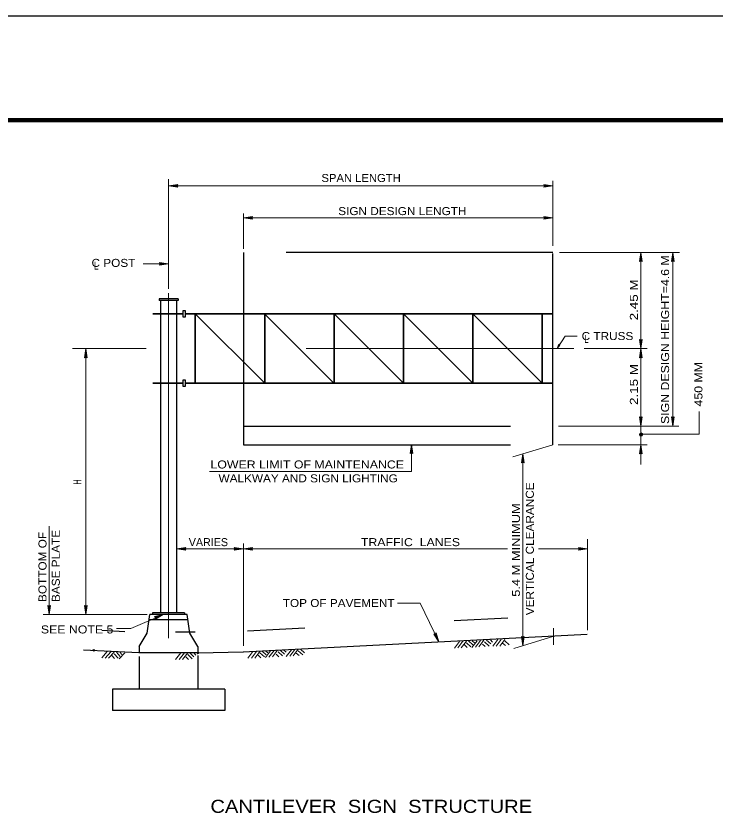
# Model space of a CAD drawing. Extents: x 312601.858 to 312602.699, y 144420.109 to 144420.704.
# Drawn here: x 312602.229 to 312602.4911, y 144420.4049 to 144420.7035 of the extents above; entities that cross this region are included whole.
import ezdxf
from ezdxf.enums import TextEntityAlignment as Align

# ---------------------------------------------------------------- set-up
doc = ezdxf.new("R2010")
doc.units = 0
doc.header["$LTSCALE"] = 0.0012
doc.header["$PDMODE"] = 32
doc.header["$PDSIZE"] = 0.0006
doc.linetypes.add('DOT_DASHED', pattern=[7.7, 5, -1.2, 0.3, -1.2])
doc.linetypes.add('LONG_DASHED', pattern=[7.5, 6, -1.5])
doc.layers.add('1', color=7, linetype='Continuous', lineweight=13)
doc.layers.add('39', color=7, linetype='Continuous', lineweight=13)

msp = doc.modelspace()

# ---------------------------------------------------------------- hatches: boundary and pattern name
at = {"layer": '39'}
for points in [[(312602.2894, 144420.6399), (312602.2897, 144420.6394), (312602.2863, 144420.6399), (312602.2897, 144420.6404)], [(312602.4272, 144420.6399), (312602.4269, 144420.6404), (312602.4303, 144420.6399), (312602.4269, 144420.6394)], [(312602.3174, 144420.6279), (312602.3177, 144420.6274), (312602.3143, 144420.6279), (312602.3177, 144420.6284)], [(312602.4272, 144420.6279), (312602.4269, 144420.6284), (312602.4303, 144420.6279), (312602.4269, 144420.6274)], [(312602.4272, 144420.6279), (312602.4269, 144420.6284), (312602.4303, 144420.6279), (312602.4269, 144420.6274)], [(312602.4633, 144420.6118), (312602.4628, 144420.6115), (312602.4633, 144420.6149), (312602.4638, 144420.6115)], [(312602.4633, 144420.6118), (312602.4628, 144420.6115), (312602.4633, 144420.6149), (312602.4638, 144420.6115)], [(312602.4753, 144420.6118), (312602.4748, 144420.6115), (312602.4753, 144420.6149), (312602.4758, 144420.6115)], [(312602.4753, 144420.6118), (312602.4748, 144420.6115), (312602.4753, 144420.6149), (312602.4758, 144420.6115)], [(312602.2832, 144420.6107), (312602.2829, 144420.6112), (312602.2863, 144420.6107), (312602.2829, 144420.6102)], [(312602.2832, 144420.6107), (312602.2829, 144420.6112), (312602.2863, 144420.6107), (312602.2829, 144420.6102)], [(312602.4328, 144420.5802), (312602.433, 144420.5802), (312602.4319, 144420.5789), (312602.4326, 144420.5805)], [(312602.4633, 144420.582), (312602.4638, 144420.5823), (312602.4633, 144420.5789), (312602.4628, 144420.5823)], [(312602.4633, 144420.582), (312602.4638, 144420.5823), (312602.4633, 144420.5789), (312602.4628, 144420.5823)], [(312602.2553, 144420.5758), (312602.2548, 144420.5755), (312602.2553, 144420.5789), (312602.2558, 144420.5755)], [(312602.2553, 144420.5758), (312602.2548, 144420.5755), (312602.2553, 144420.5789), (312602.2558, 144420.5755)], [(312602.4633, 144420.5758), (312602.4628, 144420.5755), (312602.4633, 144420.5789), (312602.4638, 144420.5755)], [(312602.4633, 144420.5758), (312602.4628, 144420.5755), (312602.4633, 144420.5789), (312602.4638, 144420.5755)], [(312602.4633, 144420.553), (312602.4638, 144420.5533), (312602.4633, 144420.5499), (312602.4628, 144420.5533)], [(312602.4633, 144420.553), (312602.4638, 144420.5533), (312602.4633, 144420.5499), (312602.4628, 144420.5533)], [(312602.4753, 144420.553), (312602.4758, 144420.5533), (312602.4753, 144420.5499), (312602.4748, 144420.5533)], [(312602.4753, 144420.553), (312602.4758, 144420.5533), (312602.4753, 144420.5499), (312602.4748, 144420.5533)], [(312602.4753, 144420.553), (312602.4758, 144420.5533), (312602.4753, 144420.5499), (312602.4748, 144420.5533)], [(312602.4639, 144420.5463, 1), (312602.4629, 144420.5471, 1)], [(312602.4631, 144420.547, 1), (312602.4635, 144420.5466, 1)], [(312602.3773, 144420.5399), (312602.3768, 144420.5396), (312602.3773, 144420.543), (312602.3778, 144420.5396)], [(312602.4633, 144420.5398), (312602.4628, 144420.5395), (312602.4633, 144420.5429), (312602.4638, 144420.5395)], [(312602.4633, 144420.5398), (312602.4628, 144420.5395), (312602.4633, 144420.5429), (312602.4638, 144420.5395)], [(312602.4191, 144420.5364), (312602.4186, 144420.5361), (312602.4191, 144420.5395), (312602.4196, 144420.5361)], [(312602.2924, 144420.5039), (312602.2927, 144420.5034), (312602.2893, 144420.5039), (312602.2927, 144420.5044)], [(312602.2924, 144420.5039), (312602.2927, 144420.5034), (312602.2893, 144420.5039), (312602.2927, 144420.5044)], [(312602.3112, 144420.5039), (312602.3109, 144420.5044), (312602.3143, 144420.5039), (312602.3109, 144420.5034)], [(312602.3112, 144420.5039), (312602.3109, 144420.5044), (312602.3143, 144420.5039), (312602.3109, 144420.5034)], [(312602.3174, 144420.5039), (312602.3177, 144420.5034), (312602.3143, 144420.5039), (312602.3177, 144420.5044)], [(312602.3174, 144420.5039), (312602.3177, 144420.5034), (312602.3143, 144420.5039), (312602.3177, 144420.5044)], [(312602.4402, 144420.5039), (312602.4399, 144420.5044), (312602.4433, 144420.5039), (312602.4399, 144420.5034)], [(312602.4402, 144420.5039), (312602.4399, 144420.5044), (312602.4433, 144420.5039), (312602.4399, 144420.5034)], [(312602.2415, 144420.4824), (312602.242, 144420.4827), (312602.2415, 144420.4793), (312602.241, 144420.4827)], [(312602.2553, 144420.4824), (312602.2558, 144420.4827), (312602.2553, 144420.4793), (312602.2548, 144420.4827)], [(312602.2814, 144420.478), (312602.281, 144420.4785), (312602.2842, 144420.4793), (312602.2814, 144420.4775)], [(312602.3862, 144420.4719), (312602.3866, 144420.4724), (312602.3876, 144420.4691), (312602.3857, 144420.4719)], [(312602.4191, 144420.4707), (312602.4196, 144420.471), (312602.4191, 144420.4676), (312602.4186, 144420.471)]]:
    msp.add_hatch(color=256, dxfattribs=at).paths.add_polyline_path(points)

# ---------------------------------------------------------------- linework, layer by layer
at = {"layer": '1', "lineweight": 25}
for p, q in [((312601.8578, 144420.7035), (312602.6988, 144420.7035)), ((312602.3933, 144420.477), (312602.4135, 144420.478)), ((312602.3159, 144420.4732), (312602.3374, 144420.4743))]:
    msp.add_line(p, q, dxfattribs=at)
at = {"layer": '1'}
for p, q in [((312602.4852, 144420.5553), (312602.4852, 144420.5469)), ((312602.4633, 144420.5469), (312602.4852, 144420.5469)), ((312602.4303, 144420.5429), (312602.4153, 144420.5383)), ((312602.2415, 144420.5124), (312602.2415, 144420.4793)), ((312602.3721, 144420.4835), (312602.3806, 144420.4835)), ((312602.3876, 144420.4691), (312602.3806, 144420.4835)), ((312602.2392, 144420.4793), (312602.2782, 144420.4793)), ((312602.3987, 144420.4694), (312602.4003, 144420.4679)), ((312602.4, 144420.467), (312602.4019, 144420.4695)), ((312602.4001, 144420.4694), (312602.4009, 144420.4687)), ((312602.4013, 144420.4671), (312602.4032, 144420.4696)), ((312602.4026, 144420.4672), (312602.4045, 144420.4697)), ((312602.4055, 144420.4697), (312602.4071, 144420.4683)), ((312602.4069, 144420.4698), (312602.4077, 144420.469)), ((312602.4078, 144420.4674), (312602.4097, 144420.4699)), ((312602.4091, 144420.4675), (312602.411, 144420.47)), ((312602.4104, 144420.4675), (312602.4123, 144420.47)), ((312602.4123, 144420.4694), (312602.414, 144420.4679)), ((312602.4307, 144420.4712), (312602.4157, 144420.4666)), ((312602.3934, 144420.4667), (312602.3953, 144420.4692)), ((312602.3947, 144420.4668), (312602.3966, 144420.4693)), ((312602.396, 144420.4668), (312602.3979, 144420.4693)), ((312602.3972, 144420.4679), (312602.3982, 144420.4669)), ((312602.3979, 144420.4687), (312602.3996, 144420.4672)), ((312602.404, 144420.4682), (312602.405, 144420.4673)), ((312602.4047, 144420.4691), (312602.4064, 144420.4675)), ((312602.4115, 144420.4686), (312602.4126, 144420.4677)), ((312602.2612, 144420.4631), (312602.2633, 144420.4654)), ((312602.2625, 144420.463), (312602.2646, 144420.4653)), ((312602.2638, 144420.463), (312602.2659, 144420.4652)), ((312602.265, 144420.4639), (312602.266, 144420.4628)), ((312602.2659, 144420.4646), (312602.2674, 144420.4629)), ((312602.2667, 144420.4652), (312602.2681, 144420.4636)), ((312602.2677, 144420.4627), (312602.2699, 144420.465)), ((312602.2681, 144420.4651), (312602.2688, 144420.4643)), ((312602.2889, 144420.4625), (312602.2909, 144420.4649)), ((312602.2902, 144420.4625), (312602.2922, 144420.4649)), ((312602.2915, 144420.4625), (312602.2935, 144420.4649)), ((312602.2927, 144420.4635), (312602.2937, 144420.4625)), ((312602.2935, 144420.4643), (312602.2951, 144420.4627)), ((312602.2943, 144420.4649), (312602.2958, 144420.4634)), ((312602.2957, 144420.4649), (312602.2965, 144420.4641)), ((312602.316, 144420.4629), (312602.3179, 144420.4654)), ((312602.3173, 144420.463), (312602.3192, 144420.4655)), ((312602.3186, 144420.463), (312602.3205, 144420.4655)), ((312602.3198, 144420.4641), (312602.3208, 144420.4631)), ((312602.3205, 144420.4649), (312602.3222, 144420.4634)), ((312602.3213, 144420.4656), (312602.3229, 144420.4642)), ((312602.3226, 144420.4632), (312602.3245, 144420.4657)), ((312602.3227, 144420.4656), (312602.3235, 144420.4649)), ((312602.3239, 144420.4633), (312602.3258, 144420.4658)), ((312602.3252, 144420.4634), (312602.3271, 144420.4659)), ((312602.3266, 144420.4644), (312602.3276, 144420.4635)), ((312602.3273, 144420.4653), (312602.329, 144420.4638)), ((312602.3281, 144420.4659), (312602.3297, 144420.4645)), ((312602.3295, 144420.466), (312602.3303, 144420.4652)), ((312602.3304, 144420.4636), (312602.3323, 144420.4661)), ((312602.3317, 144420.4637), (312602.3336, 144420.4662)), ((312602.333, 144420.4638), (312602.3349, 144420.4663)), ((312602.3341, 144420.4648), (312602.3352, 144420.4639)), ((312602.3349, 144420.4657), (312602.3366, 144420.4642)), ((312602.3357, 144420.4663), (312602.3372, 144420.4649))]:
    msp.add_line(p, q, dxfattribs=at)
at = {"layer": '1', "linetype": 'LONG_DASHED', "lineweight": 25}
for p, q in [((312602.2613, 144420.4734), (312602.2699, 144420.4729)), ((312602.2889, 144420.4728), (312602.2963, 144420.4728))]:
    msp.add_line(p, q, dxfattribs=at)
at = {"layer": '1', "lineweight": 25}
for points in [[(312602.2917, 144420.5907), (312602.2917, 144420.5932), (312602.2925, 144420.5932), (312602.2925, 144420.5907)], [(312602.2917, 144420.5647), (312602.2917, 144420.5672), (312602.2925, 144420.5672), (312602.2925, 144420.5647)]]:
    msp.add_lwpolyline(points, close=True, dxfattribs=at)
at = {"layer": '1'}
msp.add_lwpolyline([(312602.4395, 144420.5836), (312602.435, 144420.5836), (312602.4319, 144420.5789)], dxfattribs=at)
at = {"layer": '39', "lineweight": 158}
msp.add_line((312601.9088, 144420.6645), (312602.6838, 144420.6645), dxfattribs=at)
at = {"layer": '39'}
for p, q in [((312602.2863, 144420.6424), (312602.2863, 144420.6013)), ((312602.4303, 144420.6399), (312602.2863, 144420.6399)), ((312602.4303, 144420.6174), (312602.4303, 144420.6418)), ((312602.3143, 144420.6295), (312602.3143, 144420.6163)), ((312602.4303, 144420.6279), (312602.3143, 144420.6279)), ((312602.4778, 144420.6149), (312602.4328, 144420.6149)), ((312602.4633, 144420.5789), (312602.4633, 144420.6149)), ((312602.4753, 144420.5499), (312602.4753, 144420.6149)), ((312602.2768, 144420.6107), (312602.2863, 144420.6107)), ((312602.4263, 144420.5919), (312602.4263, 144420.5659)), ((312602.2779, 144420.5789), (312602.2503, 144420.5789)), ((312602.2553, 144420.4793), (312602.2553, 144420.5789)), ((312602.4421, 144420.5789), (312602.4657, 144420.5789)), ((312602.4633, 144420.5499), (312602.4633, 144420.5789)), ((312602.4325, 144420.5499), (312602.4776, 144420.5499)), ((312602.4323, 144420.5429), (312602.4657, 144420.5429)), ((312602.4191, 144420.4676), (312602.4191, 144420.5395)), ((312602.3143, 144420.5059), (312602.3143, 144420.4676)), ((312602.4433, 144420.5075), (312602.4433, 144420.4734)), ((312602.3143, 144420.5039), (312602.2893, 144420.5039)), ((312602.4133, 144420.5039), (312602.3143, 144420.5039)), ((312602.4433, 144420.5039), (312602.4249, 144420.5039)), ((312602.2863, 144420.4782), (312602.2863, 144420.4995)), ((312602.3143, 144420.4888), (312602.3143, 144420.4686)), ((312602.2863, 144420.4859), (312602.2863, 144420.4705)), ((312602.2721, 144420.4741), (312602.2841, 144420.4792)), ((312602.2721, 144420.4741), (312602.2667, 144420.4741)), ((312602.4306, 144420.4679), (312602.4306, 144420.4742)), ((312602.3144, 144420.4649), (312602.3143, 144420.4649))]:
    msp.add_line(p, q, dxfattribs=at)
at = {"layer": '39', "linetype": 'LONG_DASHED', "lineweight": 25}
for p, q in [((312602.4303, 144420.6149), (312602.3144, 144420.6149)), ((312602.3144, 144420.6149), (312602.3144, 144420.5429)), ((312602.4303, 144420.5429), (312602.4303, 144420.6145)), ((312602.3144, 144420.5499), (312602.4303, 144420.5499)), ((312602.3144, 144420.5429), (312602.4303, 144420.5429)), ((312602.2753, 144420.4636), (312602.2753, 144420.4513)), ((312602.2973, 144420.4639), (312602.2973, 144420.4513)), ((312602.3073, 144420.4513), (312602.2653, 144420.4513)), ((312602.2653, 144420.4513), (312602.2653, 144420.4433)), ((312602.3073, 144420.4513), (312602.3073, 144420.4433)), ((312602.3073, 144420.4433), (312602.2653, 144420.4433))]:
    msp.add_line(p, q, dxfattribs=at)
at = {"layer": '39', "linetype": 'DOT_DASHED'}
for p, q in [((312602.2863, 144420.5997), (312602.2863, 144420.473)), ((312602.4378, 144420.5789), (312602.2793, 144420.5789)), ((312602.4348, 144420.5789), (312602.4382, 144420.5789))]:
    msp.add_line(p, q, dxfattribs=at)
at = {"layer": '39', "lineweight": 25}
for p, q in [((312602.2899, 144420.5975), (312602.2827, 144420.5975)), ((312602.2827, 144420.5975), (312602.2827, 144420.5969)), ((312602.2899, 144420.5969), (312602.2827, 144420.5969)), ((312602.2833, 144420.5969), (312602.2833, 144420.4799)), ((312602.2893, 144420.5969), (312602.2893, 144420.4799)), ((312602.2899, 144420.5975), (312602.2899, 144420.5969)), ((312602.2783, 144420.4723), (312602.2793, 144420.4793)), ((312602.2933, 144420.4793), (312602.2793, 144420.4793)), ((312602.2923, 144420.4799), (312602.2803, 144420.4799)), ((312602.2803, 144420.4799), (312602.2803, 144420.4793)), ((312602.2923, 144420.4799), (312602.2923, 144420.4793)), ((312602.2943, 144420.4723), (312602.2933, 144420.4793)), ((312602.2936, 144420.4773), (312602.279, 144420.4773)), ((312602.2753, 144420.4673), (312602.2783, 144420.4723)), ((312602.2973, 144420.4673), (312602.2943, 144420.4723)), ((312602.2753, 144420.4673), (312602.2753, 144420.4649)), ((312602.2973, 144420.4673), (312602.2973, 144420.4649))]:
    msp.add_line(p, q, dxfattribs=at)
at = {"layer": '39', "lineweight": 35}
for p, q in [((312602.2917, 144420.5919), (312602.2804, 144420.5919)), ((312602.4303, 144420.5919), (312602.2926, 144420.5919)), ((312602.2963, 144420.5919), (312602.2963, 144420.5659)), ((312602.3223, 144420.5659), (312602.2963, 144420.5919)), ((312602.3482, 144420.5659), (312602.3222, 144420.5919)), ((312602.3223, 144420.5919), (312602.3223, 144420.5659)), ((312602.3483, 144420.5919), (312602.3483, 144420.5659)), ((312602.3743, 144420.5659), (312602.3483, 144420.5919)), ((312602.3743, 144420.5919), (312602.3743, 144420.5659)), ((312602.4003, 144420.5659), (312602.3743, 144420.5919)), ((312602.4003, 144420.5919), (312602.4003, 144420.5659)), ((312602.4263, 144420.5659), (312602.4003, 144420.5919)), ((312602.4263, 144420.5659), (312602.4263, 144420.5919)), ((312602.2804, 144420.5659), (312602.2917, 144420.5659)), ((312602.2925, 144420.5659), (312602.4303, 144420.5659))]:
    msp.add_line(p, q, dxfattribs=at)
at = {"layer": '39'}
for points in [[(312602.2894, 144420.6399), (312602.2897, 144420.6394), (312602.2863, 144420.6399), (312602.2897, 144420.6404)], [(312602.4272, 144420.6399), (312602.4269, 144420.6404), (312602.4303, 144420.6399), (312602.4269, 144420.6394)], [(312602.3174, 144420.6279), (312602.3177, 144420.6274), (312602.3143, 144420.6279), (312602.3177, 144420.6284)], [(312602.4272, 144420.6279), (312602.4269, 144420.6284), (312602.4303, 144420.6279), (312602.4269, 144420.6274)], [(312602.4272, 144420.6279), (312602.4269, 144420.6284), (312602.4303, 144420.6279), (312602.4269, 144420.6274)], [(312602.4633, 144420.6118), (312602.4628, 144420.6115), (312602.4633, 144420.6149), (312602.4638, 144420.6115)], [(312602.4633, 144420.6118), (312602.4628, 144420.6115), (312602.4633, 144420.6149), (312602.4638, 144420.6115)], [(312602.4753, 144420.6118), (312602.4748, 144420.6115), (312602.4753, 144420.6149), (312602.4758, 144420.6115)], [(312602.4753, 144420.6118), (312602.4748, 144420.6115), (312602.4753, 144420.6149), (312602.4758, 144420.6115)], [(312602.2832, 144420.6107), (312602.2829, 144420.6112), (312602.2863, 144420.6107), (312602.2829, 144420.6102)], [(312602.2832, 144420.6107), (312602.2829, 144420.6112), (312602.2863, 144420.6107), (312602.2829, 144420.6102)], [(312602.4328, 144420.5802), (312602.433, 144420.5802), (312602.4319, 144420.5789), (312602.4326, 144420.5805)], [(312602.4633, 144420.582), (312602.4638, 144420.5823), (312602.4633, 144420.5789), (312602.4628, 144420.5823)], [(312602.4633, 144420.582), (312602.4638, 144420.5823), (312602.4633, 144420.5789), (312602.4628, 144420.5823)], [(312602.2553, 144420.5758), (312602.2548, 144420.5755), (312602.2553, 144420.5789), (312602.2558, 144420.5755)], [(312602.2553, 144420.5758), (312602.2548, 144420.5755), (312602.2553, 144420.5789), (312602.2558, 144420.5755)], [(312602.4633, 144420.5758), (312602.4628, 144420.5755), (312602.4633, 144420.5789), (312602.4638, 144420.5755)], [(312602.4633, 144420.5758), (312602.4628, 144420.5755), (312602.4633, 144420.5789), (312602.4638, 144420.5755)], [(312602.4633, 144420.553), (312602.4638, 144420.5533), (312602.4633, 144420.5499), (312602.4628, 144420.5533)], [(312602.4633, 144420.553), (312602.4638, 144420.5533), (312602.4633, 144420.5499), (312602.4628, 144420.5533)], [(312602.4753, 144420.553), (312602.4758, 144420.5533), (312602.4753, 144420.5499), (312602.4748, 144420.5533)], [(312602.4753, 144420.553), (312602.4758, 144420.5533), (312602.4753, 144420.5499), (312602.4748, 144420.5533)], [(312602.4753, 144420.553), (312602.4758, 144420.5533), (312602.4753, 144420.5499), (312602.4748, 144420.5533)], [(312602.3773, 144420.5399), (312602.3768, 144420.5396), (312602.3773, 144420.543), (312602.3778, 144420.5396)], [(312602.4633, 144420.5398), (312602.4628, 144420.5395), (312602.4633, 144420.5429), (312602.4638, 144420.5395)], [(312602.4633, 144420.5398), (312602.4628, 144420.5395), (312602.4633, 144420.5429), (312602.4638, 144420.5395)], [(312602.4191, 144420.5364), (312602.4186, 144420.5361), (312602.4191, 144420.5395), (312602.4196, 144420.5361)], [(312602.2924, 144420.5039), (312602.2927, 144420.5034), (312602.2893, 144420.5039), (312602.2927, 144420.5044)], [(312602.2924, 144420.5039), (312602.2927, 144420.5034), (312602.2893, 144420.5039), (312602.2927, 144420.5044)], [(312602.3112, 144420.5039), (312602.3109, 144420.5044), (312602.3143, 144420.5039), (312602.3109, 144420.5034)], [(312602.3112, 144420.5039), (312602.3109, 144420.5044), (312602.3143, 144420.5039), (312602.3109, 144420.5034)], [(312602.3174, 144420.5039), (312602.3177, 144420.5034), (312602.3143, 144420.5039), (312602.3177, 144420.5044)], [(312602.3174, 144420.5039), (312602.3177, 144420.5034), (312602.3143, 144420.5039), (312602.3177, 144420.5044)], [(312602.4402, 144420.5039), (312602.4399, 144420.5044), (312602.4433, 144420.5039), (312602.4399, 144420.5034)], [(312602.4402, 144420.5039), (312602.4399, 144420.5044), (312602.4433, 144420.5039), (312602.4399, 144420.5034)], [(312602.2415, 144420.4824), (312602.242, 144420.4827), (312602.2415, 144420.4793), (312602.241, 144420.4827)], [(312602.2553, 144420.4824), (312602.2558, 144420.4827), (312602.2553, 144420.4793), (312602.2548, 144420.4827)], [(312602.2814, 144420.478), (312602.281, 144420.4785), (312602.2842, 144420.4793), (312602.2814, 144420.4775)], [(312602.3862, 144420.4719), (312602.3866, 144420.4724), (312602.3876, 144420.4691), (312602.3857, 144420.4719)], [(312602.4191, 144420.4707), (312602.4196, 144420.471), (312602.4191, 144420.4676), (312602.4186, 144420.471)]]:
    msp.add_lwpolyline(points, close=True, dxfattribs=at)
for points in [[(312602.4633, 144420.5355), (312602.4633, 144420.5429), (312602.4633, 144420.5499)], [(312602.3016, 144420.5329), (312602.3773, 144420.5329), (312602.3773, 144420.5429)]]:
    msp.add_lwpolyline(points, dxfattribs=at)
at = {"layer": '39', "lineweight": 25}
for points in [[(312602.2974, 144420.4649), (312602.3142, 144420.4653), (312602.4432, 144420.4719)], [(312602.2974, 144420.4649), (312602.2751, 144420.4649), (312602.2544, 144420.466)]]:
    msp.add_lwpolyline(points, dxfattribs=at)
at = {"layer": '39'}
for centre, radius in [((312602.4634, 144420.5467), 0.00064), ((312602.4633, 144420.5468), 0.000283)]:
    msp.add_circle(centre, radius, dxfattribs=at)
for p in [(312602.2582, 144420.4659), (312602.2973, 144420.4649)]:
    msp.add_point(p, dxfattribs=at)

# ---------------------------------------------------------------- texts
at = {"layer": '1'}
for s, width, p in [('SPAN LENGTH', 1.05, (312602.35845, 144420.6413)), ('SIGN DESIGN LENGTH', 1.1, (312602.3739, 144420.6289)), ('C POST', 1.1, (312602.2656, 144420.6095)), ('L', 0.75, (312602.25915, 144420.6085)), ('C TRUSS', 1.1, (312602.4508, 144420.5821)), ('L', 0.75, (312602.44295, 144420.581)), ('TOP OF PAVEMENT', 1.1, (312602.35005, 144420.4821))]:
    msp.add_text(s, height=0.003, dxfattribs=dict(at, width=width)).set_placement(p, align=Align.CENTER)
for s, width, p in [('2.45 M', 1.25, (312602.4622, 144420.59715)), ('2.15 M ', 1.25, (312602.4622, 144420.56615)), ('450 MM', 1.15, (312602.4864, 144420.56555)), ('H', 0.6, (312602.2536, 144420.52895)), ('VERTICAL CLEARANCE', 1.1, (312602.4232, 144420.5039)), ('5.4 M MINIMUM', 1.2, (312602.418, 144420.50345))]:
    msp.add_text(s, height=0.003, rotation=90, dxfattribs=dict(at, width=width)).set_placement(p, align=Align.CENTER)
at = {"layer": '1', "width": 1.1}
for s, p in [('BOTTOM OF', (312602.2405, 144420.484)), ('BASE PLATE', (312602.2455, 144420.484))]:
    msp.add_text(s, height=0.003, rotation=90, dxfattribs=at).set_placement(p)
at = {"layer": '1'}
msp.add_text('VARIES', height=0.003, dxfattribs=at).set_placement((312602.3012, 144420.5049), align=Align.CENTER)
at = {"layer": '1', "width": 1.15}
msp.add_text('SEE NOTE 5', height=0.003, dxfattribs=at).set_placement((312602.2384, 144420.4722))
at = {"layer": '39', "width": 1.15}
msp.add_text('SIGN DESIGN HEIGHT=4.6 M', height=0.003, rotation=90, dxfattribs=at).set_placement((312602.4739, 144420.58225), align=Align.CENTER)
at = {"layer": '39'}
for s, height, width, p in [('LOWER LIMIT OF MAINTENANCE', 0.003, 1.15, (312602.33825, 144420.534)), ('WALKWAY AND SIGN LIGHTING', 0.003, 1.1, (312602.3386, 144420.5288)), ('TRAFFIC  LANES', 0.003, 1.15, (312602.37695, 144420.5049)), ('CANTILEVER  SIGN  STRUCTURE', 0.0049, 1.15, (312602.36225, 144420.405))]:
    msp.add_text(s, height=height, dxfattribs=dict(at, width=width)).set_placement(p, align=Align.CENTER)

doc.saveas('drawing.dxf')
